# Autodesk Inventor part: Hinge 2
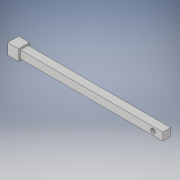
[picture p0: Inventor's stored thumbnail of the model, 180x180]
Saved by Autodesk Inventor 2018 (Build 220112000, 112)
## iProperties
Created: 2017-07
Part Number: Hinge 2
Material: Generic
Document SubType Name: Modeling
Designer: 17046589
Density: 1 g/cm^3
Appearance: Default
Author: 17046589
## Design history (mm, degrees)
sketch "Sketch1"
  geometry: L1 (0, 0)-(-10, 0); L2 (-10, 0)-(-10, -10); L3 (-10, -10)-(0, -10); L4 (0, -10)-(0, 0)
  constraints: 8 end point, 3 perpendicular, 1 horizontal
  dimensions: "d0" = 10 distance of L1.start L1.end; "d1" = 10 distance of L1.end L2.end
extrude "Extrusion1" new body sketch "Sketch1" distance "d2" = 10; taper "d3" = 0 deg
sketch "Sketch2"
  geometry: L1 (1.386, 8.512)-(8.528, 8.512); L2 (8.528, 8.512)-(8.528, 1.402); L3 (8.528, 1.402)-(1.386, 1.402); L4 (1.386, 1.402)-(1.386, 8.512); 1 further point
  constraints: 8 end point, 2 parallel, 1 horizontal, 1 perpendicular
extrude "Extrusion2" join sketch "Sketch2" distance "d4" = 130; taper "d5" = 0 deg
sketch "Sketch3"
  geometry: C1 r 2.204 at (121.075, 3.598); 1 further point
  constraints: 1 centre point
extrude "Extrusion3" cut sketch "Sketch3" distance "d6" = 130; taper "d7" = 0 deg
body "Solid1"
